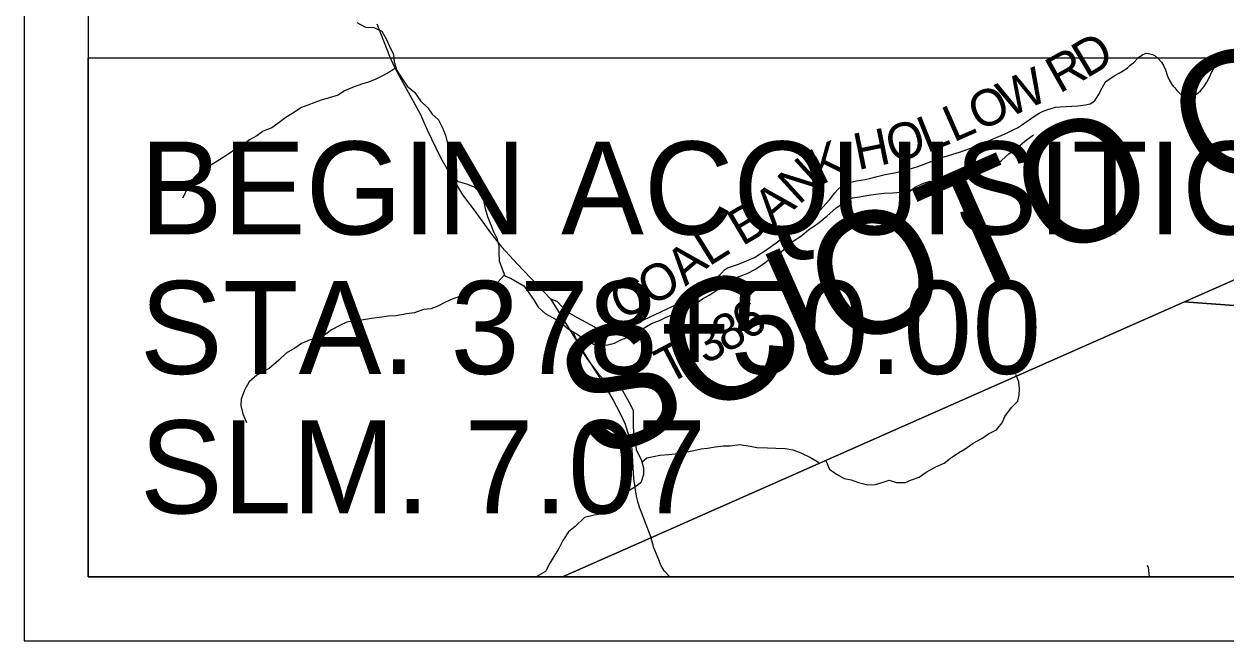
# Model space of a CAD drawing. Extents: x 0 to 34, y 0 to 22.
# Drawn here: x 2 to 3.875, y 14 to 14.962 of the extents above; entities that cross this region are included whole.
import ezdxf

# ---------------------------------------------------------------- set-up
doc = ezdxf.new("R2010")
doc.units = 0
for name, color, linetype in [('GM_X_County_Road', 7, 'Continuous'), ('GM_X_County_Text', 7, 'Continuous'), ('GM_X_Minor_River', 7, 'Continuous'), ('GM_X_Township_Road', 7, 'Continuous'), ('GM_X_Township_Road_Text', 7, 'Continuous'), ('GM_X_Unincorporated', 7, 'Continuous'), ('SH_Cut_Line', 7, 'Continuous'), ('SH_Data', 7, 'Continuous'), ('SH_Masking', 7, 'Continuous'), ('SH_Text', 7, 'Continuous')]:
    doc.layers.add(name, color=color, linetype=linetype)

msp = doc.modelspace()

# ---------------------------------------------------------------- linework, layer by layer
at = {"layer": 'GM_X_County_Road'}
for points in [[(2.5502, 14.9621), (2.5617, 14.9332), (2.5698, 14.9116), (2.5768, 14.8967), (2.5884, 14.8754), (2.6177, 14.8216), (2.629, 14.7966), (2.6496, 14.7539), (2.6613, 14.7331), (2.684, 14.6953), (2.7018, 14.6714), (2.7274, 14.6363), (2.7448, 14.6146), (2.7699, 14.5872), (2.8212, 14.5336), (2.8546, 14.4798), (2.8774, 14.4424), (2.9057, 14.3975), (2.9186, 14.3753), (2.9243, 14.3654), (2.9332, 14.3474), (2.9377, 14.3377), (2.9409, 14.3276), (2.9439, 14.3185), (2.9467, 14.308), (2.9482, 14.2977), (2.9506, 14.2534), (2.9524, 14.2391), (2.9546, 14.2259), (2.9567, 14.2176), (2.9599, 14.2077), (2.9629, 14.1997), (2.966, 14.1912), (2.978, 14.1604)], [(3.007, 14.1), (2.9988, 14.109), (2.9936, 14.1172), (2.9889, 14.129), (2.9821, 14.1453), (2.978, 14.1604)]]:
    msp.add_lwpolyline(points, dxfattribs=at)
at = {"layer": 'GM_X_Minor_River'}
for points in [[(2.5192, 14.964), (2.5328, 14.9571), (2.5456, 14.9562), (2.5581, 14.9508), (2.5652, 14.9375), (2.57, 14.9273), (2.576, 14.9143), (2.5771, 14.9026), (2.5815, 14.8893), (2.5883, 14.879), (2.5976, 14.8649), (2.6093, 14.855), (2.6183, 14.842), (2.6299, 14.8313), (2.6363, 14.821), (2.6465, 14.8123), (2.6524, 14.8008), (2.6573, 14.7887), (2.661, 14.7735), (2.6628, 14.7613), (2.665, 14.7477), (2.666, 14.737), (2.6671, 14.7268), (2.6773, 14.7161), (2.6901, 14.7126), (2.7018, 14.708), (2.7134, 14.6969), (2.7168, 14.6867), (2.7194, 14.6741), (2.7231, 14.6616), (2.7279, 14.6487), (2.732, 14.638), (2.7376, 14.6281), (2.7405, 14.6156), (2.7405, 14.6057), (2.7412, 14.5924), (2.7445, 14.5826), (2.7501, 14.5693), (2.7599, 14.565), (2.7795, 14.5535), (2.7862, 14.544), (2.7956, 14.5307), (2.802, 14.5204), (2.8129, 14.5105), (2.8242, 14.5043), (2.8362, 14.4974), (2.8494, 14.4863), (2.8626, 14.4783), (2.8743, 14.4703), (2.8882, 14.4626), (2.9003, 14.4606), (2.9101, 14.4617), (2.9211, 14.4643), (2.9306, 14.4695), (2.9431, 14.474), (2.9553, 14.4808), (2.9685, 14.4887), (2.9784, 14.4951), (2.9909, 14.4995)], [(2.5801, 14.8934), (2.5705, 14.887), (2.558, 14.8803), (2.5485, 14.8758), (2.5375, 14.8709), (2.5265, 14.868), (2.5125, 14.8627), (2.4996, 14.8575), (2.4901, 14.8511), (2.4761, 14.8466), (2.4636, 14.8429), (2.4534, 14.8396), (2.4428, 14.8355), (2.4325, 14.8314), (2.4177, 14.8216), (2.4082, 14.816), (2.3961, 14.8069), (2.3866, 14.8002), (2.3729, 14.7945), (2.3631, 14.7874), (2.3517, 14.781), (2.3418, 14.7739), (2.33, 14.7667), (2.3179, 14.7585), (2.3046, 14.7498), (2.2887, 14.7404), (2.2773, 14.7337), (2.2662, 14.7235), (2.2586, 14.7137), (2.254, 14.7035), (2.2471, 14.6902)], [(2.9909, 14.4995), (3.0004, 14.504), (3.0103, 14.5085), (3.0201, 14.5126), (3.0334, 14.5179), (3.0463, 14.525), (3.0584, 14.5336), (3.0687, 14.5393), (3.0789, 14.546), (3.0888, 14.5532), (3.1067, 14.5648), (3.1184, 14.5693), (3.129, 14.5734), (3.14, 14.579), (3.1533, 14.5877), (3.1632, 14.5956), (3.1765, 14.6031), (3.1894, 14.614), (3.1997, 14.6231), (3.213, 14.6321), (3.224, 14.6415), (3.2373, 14.6505), (3.2521, 14.6622), (3.2669, 14.675), (3.2829, 14.6855), (3.2924, 14.6908), (3.3033, 14.6922), (3.3173, 14.6948), (3.3283, 14.6963), (3.3412, 14.6981), (3.3548, 14.6987), (3.3677, 14.6994), (3.379, 14.6997), (3.3912, 14.7084), (3.4033, 14.7136), (3.4128, 14.7166), (3.4256, 14.7146), (3.4411, 14.7123), (3.4509, 14.7152), (3.4619, 14.7182), (3.4718, 14.7204), (3.482, 14.7253), (3.4938, 14.7305), (3.5063, 14.7361), (3.5158, 14.7418), (3.5253, 14.7497), (3.5359, 14.7595), (3.5492, 14.7689), (3.561, 14.779), (3.5743, 14.7888)], [(2.7495, 14.5706), (2.7387, 14.5587), (2.7262, 14.5512), (2.7144, 14.5494), (2.7012, 14.5453), (2.6913, 14.5415), (2.6815, 14.5374), (2.6689, 14.5333), (2.6576, 14.5281), (2.6454, 14.5217), (2.6344, 14.518), (2.6231, 14.5169), (2.6091, 14.5113), (2.5966, 14.5099), (2.5803, 14.5069), (2.5682, 14.5062), (2.558, 14.5048), (2.5421, 14.5026), (2.5262, 14.5), (2.5144, 14.499), (2.5035, 14.4971), (2.4925, 14.4919), (2.4796, 14.4848), (2.4693, 14.4772), (2.456, 14.4716), (2.4462, 14.4694), (2.4325, 14.4638), (2.4223, 14.4563), (2.409, 14.4488), (2.3976, 14.4378), (2.3824, 14.4247), (2.3725, 14.4198), (2.363, 14.4145), (2.3513, 14.404), (2.3436, 14.3911), (2.3386, 14.3771), (2.3382, 14.3673), (2.3411, 14.354), (2.3471, 14.3403)], [(2.8564, 14.4821), (2.8595, 14.4738), (2.864, 14.4635), (2.8689, 14.4536), (2.8779, 14.4403), (2.8959, 14.4159), (2.9068, 14.4048), (2.9185, 14.4029), (2.9309, 14.3952), (2.9384, 14.3811), (2.9455, 14.3689), (2.95, 14.3591), (2.9503, 14.3458), (2.9502, 14.3333), (2.9513, 14.3215), (2.9535, 14.3116), (2.9549, 14.298), (2.9624, 14.2831), (2.9664, 14.2698), (2.9664, 14.2596), (2.9621, 14.2467), (2.9511, 14.2388), (2.9413, 14.2332), (2.9291, 14.2203), (2.9245, 14.2105), (2.9108, 14.2), (2.8994, 14.1978), (2.8892, 14.1959), (2.8741, 14.1926), (2.8596, 14.1783), (2.8494, 14.17), (2.8406, 14.1568), (2.8341, 14.1443), (2.8261, 14.1314), (2.8203, 14.1212), (2.8131, 14.1084), (2.7989, 14.1)], [(3.2508, 14.2807), (3.2564, 14.2678), (3.2673, 14.2598), (3.2794, 14.2533), (3.2899, 14.2514), (3.3013, 14.2471), (3.316, 14.2436), (3.3281, 14.244), (3.3398, 14.2473), (3.3493, 14.2507), (3.361, 14.2468), (3.3746, 14.2472), (3.3841, 14.2513), (3.3962, 14.2554), (3.4069, 14.2629), (3.422, 14.2712), (3.4353, 14.2772), (3.4452, 14.2851), (3.4581, 14.2938), (3.468, 14.2994), (3.4805, 14.3085), (3.4938, 14.3156), (3.5044, 14.3227), (3.5165, 14.3291), (3.5257, 14.3401), (3.5299, 14.3499), (3.5401, 14.3639), (3.55, 14.3737), (3.552, 14.3832), (3.5524, 14.3931), (3.5517, 14.4037), (3.5468, 14.4155)], [(2.9637, 14.2789), (2.9715, 14.2857), (2.9817, 14.2875), (2.9915, 14.2894), (3.0059, 14.2908), (3.0157, 14.2915), (3.026, 14.2934), (3.0449, 14.297), (3.0562, 14.2996), (3.0661, 14.3003), (3.0782, 14.3025), (3.0903, 14.304), (3.1013, 14.3043), (3.1164, 14.3061), (3.1327, 14.3037), (3.1429, 14.3014), (3.1595, 14.3013), (3.1727, 14.3004), (3.1871, 14.3), (3.1992, 14.298), (3.2113, 14.2934), (3.2267, 14.2861), (3.2365, 14.2803), (3.2413, 14.2765)], [(3.7554, 14.1), (3.7538, 14.1151), (3.7516, 14.1178)]]:
    msp.add_lwpolyline(points, dxfattribs=at)
at = {"layer": 'GM_X_Township_Road'}
msp.add_lwpolyline([(2.8212, 14.5336), (2.8311, 14.5295), (2.8406, 14.52), (2.8483, 14.5124), (2.8625, 14.5043), (2.8895, 14.4899), (2.8948, 14.4863), (2.9003, 14.4835), (2.9047, 14.4818), (2.9083, 14.4806), (2.9128, 14.479), (2.9174, 14.4792), (2.9225, 14.4802), (2.9489, 14.4921), (3.0195, 14.5253), (3.0579, 14.5469), (3.069, 14.5556), (3.0876, 14.5736), (3.0925, 14.5785), (3.0973, 14.5819), (3.1143, 14.5872), (3.1295, 14.5934), (3.1392, 14.5977), (3.1495, 14.6043), (3.1603, 14.6112), (3.1731, 14.6207), (3.1833, 14.6284), (3.1927, 14.6351), (3.213, 14.6466), (3.2279, 14.6579), (3.2358, 14.665), (3.2413, 14.6712), (3.2562, 14.6878), (3.2645, 14.6987), (3.2692, 14.7036), (3.274, 14.7078), (3.277, 14.7099), (3.2799, 14.7115), (3.2839, 14.7133), (3.2902, 14.7151), (3.2985, 14.7171), (3.312, 14.7194), (3.3207, 14.7216), (3.3306, 14.7242), (3.3431, 14.727), (3.3579, 14.7299), (3.3739, 14.7333), (3.3939, 14.7398), (3.4317, 14.7539), (3.459, 14.762), (3.4792, 14.7693), (3.5301, 14.7907), (3.5439, 14.7972), (3.5507, 14.8006), (3.5592, 14.8065), (3.5679, 14.8123), (3.575, 14.8178), (3.5831, 14.8226), (3.5887, 14.8253), (3.5966, 14.8283), (3.6019, 14.8301), (3.6088, 14.8321), (3.6158, 14.8328), (3.6435, 14.8342), (3.6556, 14.8358), (3.6629, 14.8374), (3.6672, 14.84), (3.6708, 14.8431), (3.6759, 14.8516), (3.6817, 14.8625), (3.6866, 14.8718), (3.6902, 14.8742), (3.7005, 14.8809), (3.708, 14.8851), (3.7175, 14.891), (3.7215, 14.8938), (3.7254, 14.8976), (3.7302, 14.9015), (3.7381, 14.9098), (3.745, 14.9144), (3.7502, 14.9164), (3.7539, 14.9156), (3.7598, 14.9144), (3.7644, 14.912), (3.769, 14.9081), (3.7743, 14.9021), (3.7773, 14.897), (3.7804, 14.8904), (3.7834, 14.8805), (3.786, 14.8748), (3.7897, 14.8685), (3.7923, 14.8647), (3.7949, 14.8621), (3.7982, 14.8584), (3.803, 14.8532), (3.8085, 14.8501), (3.8135, 14.8477), (3.8192, 14.8477), (3.8247, 14.8499), (3.8289, 14.8524), (3.8347, 14.8578), (3.84, 14.8637), (3.8448, 14.8712), (3.8479, 14.8767), (3.8537, 14.8894), (3.8572, 14.896), (3.8598, 14.8993), (3.8628, 14.9039), (3.8673, 14.909), (3.9008, 14.9318)], dxfattribs=at)
at = {"layer": 'GM_X_Unincorporated'}
for points in [[(2.2853, 20.9), (2.1, 20.9), (2.1, 14.1), (2.8399, 14.1), (2.9778, 14.1609), (3.8099, 14.5285), (4.2904, 14.7408), (4.3998, 14.7897), (4.802, 14.9692), (4.4847, 15.685), (4.2937, 16.1161), (4.0882, 16.6114), (3.972, 16.8916), (3.7367, 17.4136), (3.709, 17.484), (3.4011, 18.2653), (3.1249, 18.9173), (3.0781, 19.0279), (2.9956, 19.2227), (2.9553, 19.318), (2.7473, 19.8121), (2.418, 20.5866)], [(2.8399, 14.1), (7.2132, 14.1), (7.2248, 14.3369), (7.1526, 14.3412), (6.2131, 14.3976), (4.438, 14.498), (4.2897, 14.5063), (4.1531, 14.503), (3.8099, 14.5285), (2.9778, 14.1609)]]:
    msp.add_lwpolyline(points, close=True, dxfattribs=at)
msp.add_lwpolyline([(4.0882, 16.6114), (4.2937, 16.1161), (4.4847, 15.685), (4.802, 14.9692), (4.3998, 14.7897), (4.2904, 14.7408), (3.8099, 14.5285), (4.1531, 14.503), (4.2897, 14.5063), (4.438, 14.498), (6.2131, 14.3976), (7.1526, 14.3412), (7.2248, 14.3369), (7.5073, 14.3182), (7.991, 14.2863), (8.4238, 14.2578), (8.9, 14.2264), (8.9, 20.3234)], dxfattribs=at)
at = {"layer": 'SH_Cut_Line'}
for points in [[(2.1, 20.9), (2.1, 14.1), (2.8399, 14.1), (2.9778, 14.1609), (3.8099, 14.5285), (4.2904, 14.7408), (4.3998, 14.7897), (4.802, 14.9692), (4.4847, 15.685), (4.2937, 16.1161), (4.0882, 16.6114)], [(4.0882, 16.6114), (4.2937, 16.1161), (4.4847, 15.685), (4.802, 14.9692), (4.3998, 14.7897), (4.2904, 14.7408), (3.8099, 14.5285), (2.9778, 14.1609), (2.8399, 14.1), (8.9, 14.1), (8.9, 20.9)]]:
    msp.add_lwpolyline(points, dxfattribs=at)
at = {"layer": 'SH_Data'}
for p, q in [((2, 21), (2, 14)), ((2.1, 20.9), (2.1, 14.1)), ((2.1, 14.1), (8.9, 14.1)), ((2.1, 14.1), (2.1, 14.1)), ((2, 14), (9, 14))]:
    msp.add_line(p, q, dxfattribs=at)
at = {"layer": 'SH_Masking'}
msp.add_lwpolyline([(2.1, 14.9089), (4.1319, 14.9089), (4.1319, 14.1), (2.1, 14.1)], close=True, dxfattribs=at)

# ---------------------------------------------------------------- texts
at = {"layer": 'GM_X_County_Text'}
msp.add_text('SCIOTO COUNTY', height=0.189394, rotation=23.8999, dxfattribs=at).set_placement((2.8904, 14.2774))
at = {"layer": 'GM_X_Township_Road_Text'}
for s, rotation, p in [('D', 30.7679, (3.6569, 14.8763)), ('R', 29.3165, (3.6149, 14.8527)), ('W', 24.8931, (3.5354, 14.8148)), ('O', 23.8947, (3.4887, 14.7941)), ('L', 23.8218, (3.4497, 14.7769)), ('O', 15.0931, (3.3531, 14.7449)), ('L', 21.81, (3.4082, 14.7602)), ('H', 11.5811, (3.3004, 14.734)), ('K', 25.8336, (3.2418, 14.7098)), ('N', 42.4353, (3.2085, 14.6785)), ('A', 40.3896, (3.1687, 14.6446)), ('B', 30.6783, (3.1201, 14.6147)), ('L', 32.0358, (3.0681, 14.5832)), ('A', 40.3179, (3.0317, 14.5521)), ('O', 28.3673, (2.977, 14.5211)), ('C', 23.8917, (2.93, 14.5)), ('6', 32.7871, (3.1275, 14.4669)), ('8', 30.0519, (3.0947, 14.4478)), ('3', 28.7022, (3.0627, 14.4303)), ('T', 27.8512, (3.0038, 14.399)), ('-', 28.0516, (3.0415, 14.419))]:
    msp.add_text(s, height=0.0568, rotation=rotation, dxfattribs=at).set_placement(p)
at = {"layer": 'SH_Text'}
for s, height, p in [('BEGIN ACQUISITION', 0.144931, (2.1806, 14.6337)), ('STA. 378+50.00', 0.144931, (2.1806, 14.4163)), ('SLM. 7.07', 0.14493, (2.1806, 14.1989))]:
    msp.add_text(s, height=height, rotation=360, dxfattribs=at).set_placement(p)

doc.saveas('drawing.dxf')
